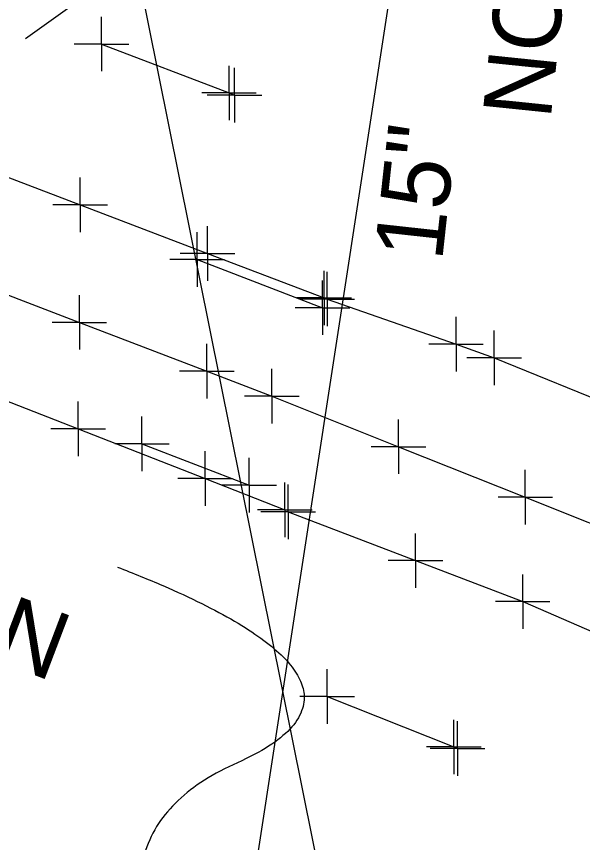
# Model space of a CAD drawing. Extents: x 0 to 1944463, y 0 to 420651.
# Drawn here: x 1942669.2 to 1942710.7, y 417839.3 to 417899.8 of the extents above; entities that cross this region are included whole.
import ezdxf

# ---------------------------------------------------------------- set-up
doc = ezdxf.new("R2010")
doc.units = 0
for name, color, linetype in [('SUR - DRG - Storm Sewer', 7, 'Continuous'), ('SUR - DRG - Storm Sewer Text', 7, 'Continuous'), ('SUR - DTM - Breaklines', 7, 'Continuous'), ('SUR - DTM - Breaklines - Points - Locators', 7, 'Continuous'), ('SUR - TR-CTRL - Pavement Marking', 7, 'Continuous'), ('SUR - TR-CTRL - Pavement Marking - Points - Locators', 7, 'Continuous'), ('SUR - UTL - Water', 7, 'Continuous')]:
    doc.layers.add(name, color=color, linetype=linetype)

msp = doc.modelspace()

# ---------------------------------------------------------------- linework, layer by layer
at = {"layer": 'SUR - DRG - Storm Sewer'}
msp.add_lwpolyline([(1942684.47, 417822.65), (1942705.05, 417956.44)], dxfattribs=at)
at = {"layer": 'SUR - DRG - Storm Sewer Text'}
for points in [[(1942669.882, 417898.211), (1942702.516, 417920.534), (1942693.666, 417950.237), (1942704, 417957.423), (1942704, 417957.423)], [(1942676.625, 417859.484), (1942698.565, 417850.998), (1942672.015, 417839.19), (1942683.534, 417822.533)]]:
    msp.add_open_spline(points, degree=2, dxfattribs=at)
at = {"layer": 'SUR - DTM - Breaklines'}
for points in [[(1942513.063, 417938.269), (1942522.461, 417934.852), (1942531.86, 417931.436), (1942541.258, 417928.019), (1942550.656, 417924.603), (1942552.438, 417923.955), (1942561.775, 417920.375), (1942571.113, 417916.795), (1942580.45, 417913.215), (1942589.787, 417909.635), (1942599.124, 417906.055), (1942608.462, 417902.475), (1942617.799, 417898.894), (1942627.136, 417895.315), (1942636.473, 417891.734), (1942645.81, 417888.154), (1942655.147, 417884.574), (1942664.485, 417880.994), (1942673.822, 417877.414), (1942683.159, 417873.834), (1942687.919, 417872.009), (1942697.207, 417868.306), (1942706.496, 417864.602), (1942715.785, 417860.899)], [(1942691.985, 417879.124), (1942701.418, 417875.806), (1942704.218, 417874.821), (1942713.477, 417871.044), (1942718.474, 417869.005), (1942727.733, 417865.227), (1942736.992, 417861.45), (1942738.626, 417860.783), (1942747.84, 417856.896), (1942751.278, 417855.446), (1942760.405, 417851.361), (1942769.533, 417847.277), (1942772.273, 417846.051)], [(1942689.117, 417863.531), (1942698.456, 417859.956), (1942706.302, 417856.953), (1942715.481, 417852.984), (1942724.659, 417849.016), (1942726.05, 417848.414), (1942735.229, 417844.446), (1942744.408, 417840.477), (1942744.901, 417840.264), (1942753.969, 417836.048), (1942763.036, 417831.832), (1942765.153, 417830.848)]]:
    msp.add_lwpolyline(points, dxfattribs=at)
at = {"layer": 'SUR - DTM - Breaklines - Points - Locators'}
for p, q in [((1942691.985, 417879.124), (1942691.985, 417881.124)), ((1942673.822, 417877.414), (1942673.822, 417879.414)), ((1942691.985, 417879.124), (1942689.985, 417879.124)), ((1942691.985, 417879.124), (1942693.985, 417879.124)), ((1942691.985, 417879.124), (1942691.985, 417877.124)), ((1942701.418, 417875.806), (1942701.418, 417877.806)), ((1942673.822, 417877.414), (1942671.822, 417877.414)), ((1942673.822, 417877.414), (1942675.822, 417877.414)), ((1942673.822, 417877.414), (1942673.822, 417875.414)), ((1942704.218, 417874.821), (1942704.218, 417876.821)), ((1942683.159, 417873.834), (1942683.159, 417875.834)), ((1942701.418, 417875.806), (1942699.418, 417875.806)), ((1942701.418, 417875.806), (1942703.418, 417875.806)), ((1942701.418, 417875.806), (1942701.418, 417873.806)), ((1942704.218, 417874.821), (1942702.218, 417874.821)), ((1942704.218, 417874.821), (1942706.218, 417874.821)), ((1942704.218, 417874.821), (1942704.218, 417872.821)), ((1942687.919, 417872.009), (1942687.919, 417874.009)), ((1942683.159, 417873.834), (1942681.159, 417873.834)), ((1942683.159, 417873.834), (1942685.159, 417873.834)), ((1942683.159, 417873.834), (1942683.159, 417871.834)), ((1942687.919, 417872.009), (1942685.919, 417872.009)), ((1942687.919, 417872.009), (1942689.919, 417872.009)), ((1942687.919, 417872.009), (1942687.919, 417870.009)), ((1942697.207, 417868.306), (1942697.207, 417870.306)), ((1942697.207, 417868.306), (1942695.207, 417868.306)), ((1942697.207, 417868.306), (1942699.207, 417868.306)), ((1942697.207, 417868.306), (1942697.207, 417866.306)), ((1942706.496, 417864.602), (1942706.496, 417866.602)), ((1942689.117, 417863.531), (1942689.117, 417865.531)), ((1942706.496, 417864.602), (1942704.496, 417864.602)), ((1942706.496, 417864.602), (1942708.496, 417864.602)), ((1942706.496, 417864.602), (1942706.496, 417862.602)), ((1942689.117, 417863.531), (1942687.117, 417863.531)), ((1942689.117, 417863.531), (1942691.117, 417863.531)), ((1942689.117, 417863.531), (1942689.117, 417861.531)), ((1942698.456, 417859.956), (1942698.456, 417861.956)), ((1942698.456, 417859.956), (1942696.456, 417859.956)), ((1942698.456, 417859.956), (1942700.456, 417859.956)), ((1942698.456, 417859.956), (1942698.456, 417857.956)), ((1942706.302, 417856.953), (1942706.302, 417858.953)), ((1942706.302, 417856.953), (1942704.302, 417856.953)), ((1942706.302, 417856.953), (1942708.302, 417856.953)), ((1942706.302, 417856.953), (1942706.302, 417854.953))]:
    msp.add_line(p, q, dxfattribs=at)
at = {"layer": 'SUR - TR-CTRL - Pavement Marking'}
for points in [[(1942510.923, 417947.437), (1942520.295, 417943.95), (1942529.667, 417940.463), (1942539.04, 417936.976), (1942548.412, 417933.49), (1942557.785, 417930.003), (1942567.157, 417926.516), (1942576.529, 417923.029), (1942577.573, 417922.641), (1942586.932, 417919.118), (1942596.291, 417915.595), (1942605.65, 417912.072), (1942609.721, 417910.54), (1942619.062, 417906.971), (1942628.403, 417903.402), (1942637.745, 417899.833), (1942647.086, 417896.264), (1942655.195, 417893.166), (1942664.536, 417889.597), (1942673.878, 417886.028), (1942683.219, 417882.459), (1942691.753, 417879.198)], [(1942509.199, 417930.569), (1942518.59, 417927.132), (1942527.981, 417923.695), (1942537.372, 417920.258), (1942539.916, 417919.327), (1942549.307, 417915.89), (1942558.698, 417912.453), (1942568.088, 417909.016), (1942577.479, 417905.579), (1942586.87, 417902.142), (1942596.261, 417898.705), (1942605.652, 417895.268), (1942615.043, 417891.832), (1942618.784, 417890.462), (1942628.141, 417886.934), (1942637.498, 417883.405), (1942646.855, 417879.877), (1942656.212, 417876.348), (1942664.415, 417873.255), (1942673.727, 417869.61), (1942683.039, 417865.965), (1942688.875, 417863.68)], [(1942675.452, 417897.802), (1942684.787, 417894.216), (1942685.19, 417894.061)], [(1942682.453, 417882.022), (1942691.637, 417878.488)], [(1942678.409, 417868.517), (1942686.255, 417865.492)], [(1942691.973, 417850.011), (1942701.262, 417846.306), (1942701.517, 417846.205)]]:
    msp.add_lwpolyline(points, dxfattribs=at)
at = {"layer": 'SUR - TR-CTRL - Pavement Marking - Points - Locators'}
for p, q in [((1942675.452, 417897.802), (1942675.452, 417899.802)), ((1942675.452, 417897.802), (1942673.452, 417897.802)), ((1942675.452, 417897.802), (1942677.452, 417897.802)), ((1942675.452, 417897.802), (1942675.452, 417895.802)), ((1942684.787, 417894.216), (1942684.787, 417896.216)), ((1942685.19, 417894.061), (1942685.19, 417896.061)), ((1942684.787, 417894.216), (1942682.787, 417894.216)), ((1942685.19, 417894.061), (1942683.19, 417894.061)), ((1942684.787, 417894.216), (1942686.787, 417894.216)), ((1942684.787, 417894.216), (1942684.787, 417892.216)), ((1942685.19, 417894.061), (1942687.19, 417894.061)), ((1942685.19, 417894.061), (1942685.19, 417892.061)), ((1942673.878, 417886.028), (1942673.878, 417888.028)), ((1942673.878, 417886.028), (1942671.878, 417886.028)), ((1942673.878, 417886.028), (1942675.878, 417886.028)), ((1942673.878, 417886.028), (1942673.878, 417884.028)), ((1942683.219, 417882.459), (1942683.219, 417884.459)), ((1942682.453, 417882.022), (1942682.453, 417884.022)), ((1942682.453, 417882.022), (1942680.453, 417882.022)), ((1942683.219, 417882.459), (1942681.219, 417882.459)), ((1942682.453, 417882.022), (1942684.453, 417882.022)), ((1942682.453, 417882.022), (1942682.453, 417880.022)), ((1942683.219, 417882.459), (1942685.219, 417882.459)), ((1942683.219, 417882.459), (1942683.219, 417880.459)), ((1942691.753, 417879.198), (1942691.753, 417881.198)), ((1942691.637, 417878.488), (1942691.637, 417880.488)), ((1942691.753, 417879.198), (1942689.753, 417879.198)), ((1942691.753, 417879.198), (1942693.753, 417879.198)), ((1942691.753, 417879.198), (1942691.753, 417877.198)), ((1942691.637, 417878.488), (1942689.637, 417878.488)), ((1942691.637, 417878.488), (1942693.637, 417878.488)), ((1942691.637, 417878.488), (1942691.637, 417876.488)), ((1942673.727, 417869.61), (1942673.727, 417871.61)), ((1942678.409, 417868.517), (1942678.409, 417870.517)), ((1942673.727, 417869.61), (1942671.727, 417869.61)), ((1942673.727, 417869.61), (1942675.727, 417869.61)), ((1942673.727, 417869.61), (1942673.727, 417867.61)), ((1942678.409, 417868.517), (1942676.409, 417868.517)), ((1942678.409, 417868.517), (1942680.409, 417868.517)), ((1942678.409, 417868.517), (1942678.409, 417866.517)), ((1942683.039, 417865.965), (1942683.039, 417867.965)), ((1942686.255, 417865.492), (1942686.255, 417867.492)), ((1942683.039, 417865.965), (1942681.039, 417865.965)), ((1942683.039, 417865.965), (1942685.039, 417865.965)), ((1942683.039, 417865.965), (1942683.039, 417863.965)), ((1942688.875, 417863.68), (1942688.875, 417865.68)), ((1942686.255, 417865.492), (1942684.255, 417865.492)), ((1942686.255, 417865.492), (1942688.255, 417865.492)), ((1942686.255, 417865.492), (1942686.255, 417863.492)), ((1942688.875, 417863.68), (1942686.875, 417863.68)), ((1942688.875, 417863.68), (1942690.875, 417863.68)), ((1942688.875, 417863.68), (1942688.875, 417861.68)), ((1942691.973, 417850.011), (1942691.973, 417852.011)), ((1942691.973, 417850.011), (1942689.973, 417850.011)), ((1942691.973, 417850.011), (1942693.973, 417850.011)), ((1942691.973, 417850.011), (1942691.973, 417848.011)), ((1942701.262, 417846.306), (1942701.262, 417848.306)), ((1942701.517, 417846.205), (1942701.517, 417848.205)), ((1942701.262, 417846.306), (1942699.262, 417846.306)), ((1942701.517, 417846.205), (1942699.517, 417846.205)), ((1942701.262, 417846.306), (1942703.262, 417846.306)), ((1942701.262, 417846.306), (1942701.262, 417844.306)), ((1942701.517, 417846.205), (1942703.517, 417846.205)), ((1942701.517, 417846.205), (1942701.517, 417844.205))]:
    msp.add_line(p, q, dxfattribs=at)
at = {"layer": 'SUR - UTL - Water'}
msp.add_lwpolyline([(1942670.552, 417940.554), (1942693.939, 417824.446)], dxfattribs=at)

# ---------------------------------------------------------------- texts
at = {"layer": 'SUR - DRG - Storm Sewer Text'}
for s, height, rotation, p in [('INACCESSIBLE COVERED JUNCTION', 4.99999, 264.11419, (1942715.602, 418011.359)), ('INACCESSIBLE COVERED JUNCTION', 4.99999, 339.20547, (1942560.304, 417893.431)), ('15"', 5, 83.76237, (1942700.395, 417881.834))]:
    msp.add_text(s, height=height, rotation=rotation, dxfattribs=at).set_placement(p)

doc.saveas('drawing.dxf')
